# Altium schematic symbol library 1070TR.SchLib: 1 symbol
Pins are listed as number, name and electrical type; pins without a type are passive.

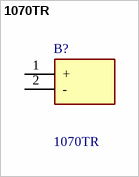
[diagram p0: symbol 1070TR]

## 1070TR
designator B?
Battery Holder (Open) Coin, 20.0mm 1 Cell SMD (SMT) Tab -50C ~ 145C; Manufacturer_Name: Keystone Electronics; Geometry.Height: 6.22mm
footprint 1070TR
pins: 1 +, 2 -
